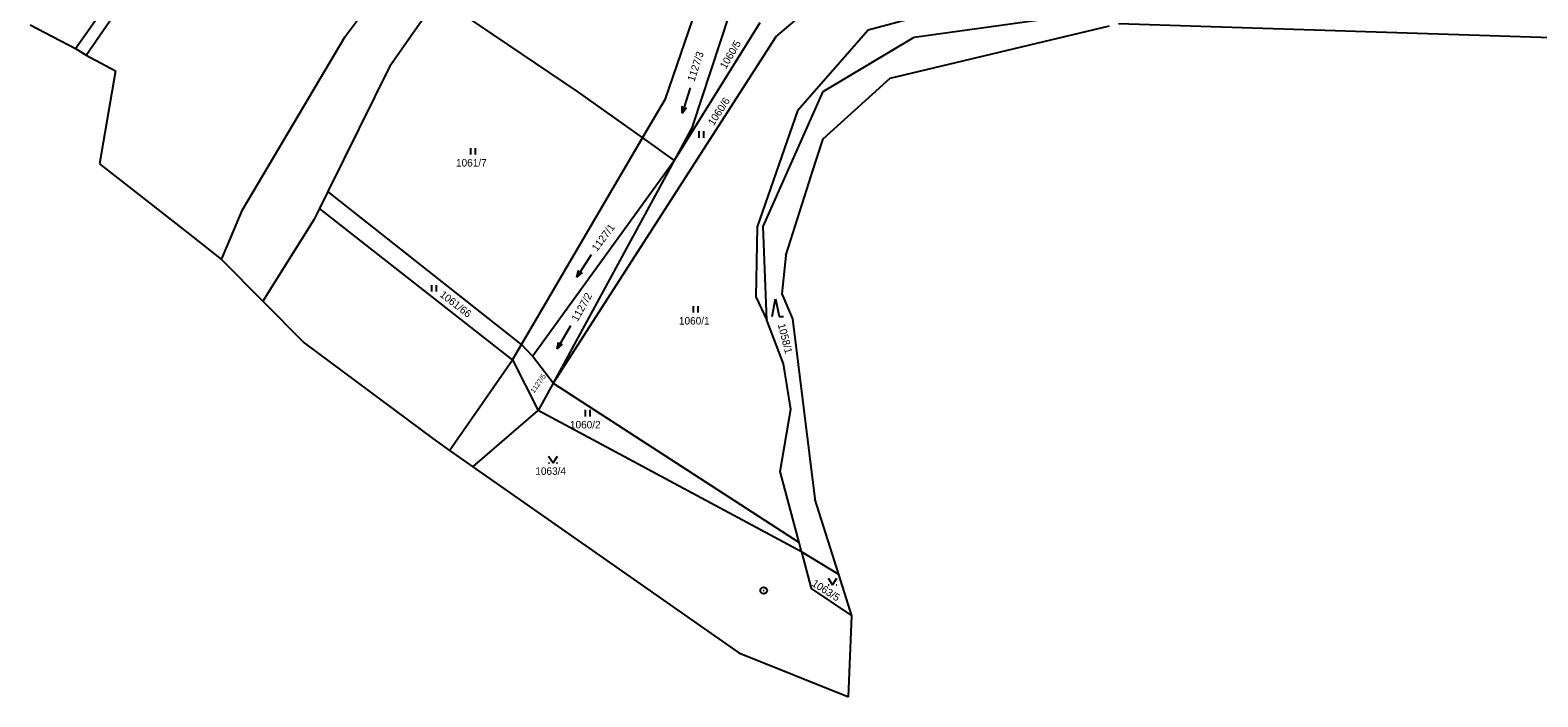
# Model space of a CAD drawing. Extents: x -794142 to -791199, y -1109267 to -1105626.
# Drawn here: x -791825.8 to -791483.8, y -1109267.2 to -1109116.1 of the extents above; entities that cross this region are included whole.
import ezdxf

# ---------------------------------------------------------------- set-up
doc = ezdxf.new("R2010")
doc.units = 0
for name, color, linetype in [('Vrstva 1', 7, 'Continuous'), ('Vrstva 14', 7, 'Continuous'), ('Vrstva 2', 7, 'Continuous'), ('Vrstva 23', 7, 'Continuous'), ('Vrstva 28', 7, 'Continuous'), ('Vrstva 4', 7, 'Continuous')]:
    doc.layers.add(name, color=color, linetype=linetype)

msp = doc.modelspace()

# ---------------------------------------------------------------- linework, layer by layer
at = {"layer": 'Vrstva 1'}
for p, q in [((-791815.6, -1109120.24), (-791790.6, -1109084.9)), ((-791813.15, -1109121.71), (-791788.95, -1109086.5)), ((-791754.39, -1109117.47), (-791732.12, -1109087.48)), ((-791587.21, -1109103.02), (-791635.72, -1109116.06)), ((-791656.65, -1109117.54), (-791641.85, -1109104.99)), ((-791744.18, -1109124.03), (-791733.38, -1109108.6)), ((-791733.38, -1109108.6), (-791701.74, -1109129.93)), ((-791681.73, -1109131.6), (-791673.74, -1109108.45)), ((-791675.53, -1109137.75), (-791667.17, -1109112.51)), ((-791625.28, -1109117.66), (-791582.71, -1109111.72)), ((-791777.65, -1109156.78), (-791754.39, -1109117.47)), ((-791656.65, -1109117.54), (-791707.2, -1109196.07)), ((-791660.34, -1109114.37), (-791679.78, -1109145.58)), ((-791635.72, -1109116.06), (-791651.74, -1109134.32)), ((-791645.91, -1109129.97), (-791625.28, -1109117.66)), ((-791744.18, -1109124.03), (-791758.35, -1109152.66)), ((-791701.74, -1109129.93), (-791686.94, -1109140.48)), ((-791659.53, -1109160.6), (-791645.91, -1109129.97)), ((-791686.94, -1109140.48), (-791681.73, -1109131.6)), ((-791651.74, -1109134.32), (-791660.94, -1109160.64)), ((-791675.53, -1109137.75), (-791679.78, -1109145.58)), ((-791714.38, -1109187.3), (-791686.94, -1109140.48)), ((-791686.94, -1109140.48), (-791679.78, -1109145.58)), ((-791711.87, -1109189.98), (-791679.78, -1109145.58)), ((-791679.78, -1109145.58), (-791707.2, -1109196.07)), ((-791758.35, -1109152.66), (-791760.23, -1109156.47)), ((-791714.38, -1109187.3), (-791758.35, -1109152.66)), ((-791781.19, -1109165.05), (-791777.65, -1109156.78)), ((-791760.23, -1109156.47), (-791761.5, -1109159.03)), ((-791716.43, -1109190.8), (-791760.23, -1109156.47)), ((-791761.5, -1109159.03), (-791773.09, -1109177.5)), ((-791660.94, -1109160.64), (-791661.25, -1109176.51)), ((-791658.73, -1109181.8), (-791659.53, -1109160.6)), ((-791782.44, -1109168.07), (-791781.19, -1109165.05)), ((-791661.25, -1109176.51), (-791658.73, -1109181.8)), ((-791654.92, -1109191.68), (-791658.73, -1109181.8)), ((-791716.43, -1109190.8), (-791714.38, -1109187.3)), ((-791711.87, -1109189.98), (-791714.38, -1109187.3)), ((-791716.43, -1109190.8), (-791710.57, -1109202.27)), ((-791707.2, -1109196.07), (-791711.87, -1109189.98)), ((-791653.31, -1109201.98), (-791654.92, -1109191.68)), ((-791707.2, -1109196.07), (-791710.57, -1109202.27)), ((-791707.2, -1109196.07), (-791651.41, -1109232.19)), ((-791650.84, -1109234.31), (-791710.57, -1109202.27)), ((-791655.69, -1109216.11), (-791653.31, -1109201.98)), ((-791651.41, -1109232.19), (-791655.69, -1109216.11)), ((-791650.84, -1109234.31), (-791651.41, -1109232.19)), ((-791650.84, -1109234.31), (-791648.67, -1109242.66)), ((-791642.41, -1109239.49), (-791650.84, -1109234.31)), ((-791648.67, -1109242.66), (-791639.45, -1109248.85))]:
    msp.add_line(p, q, dxfattribs=at)
at = {"layer": 'Vrstva 2'}
for p, q in [((-791730.72, -1109211.36), (-791716.43, -1109190.8)), ((-791725.4, -1109215.08), (-791710.57, -1109202.27))]:
    msp.add_line(p, q, dxfattribs=at)
at = {"layer": 'Vrstva 23'}
for p, q in [((-791676.085, -1109129.119), (-791677.894, -1109134.84)), ((-791677.894, -1109134.84), (-791677.918, -1109133.259)), ((-791677.894, -1109134.84), (-791676.965, -1109133.56)), ((-791674.1, -1109140.43), (-791674.1, -1109138.93)), ((-791673.1, -1109138.93), (-791673.1, -1109140.43)), ((-791725.91, -1109144.27), (-791725.91, -1109142.77)), ((-791724.91, -1109142.77), (-791724.91, -1109144.27)), ((-791698.582, -1109166.957), (-791701.797, -1109172.022)), ((-791701.797, -1109172.022), (-791701.415, -1109170.488)), ((-791701.797, -1109172.022), (-791700.571, -1109171.024)), ((-791734.72, -1109175.33), (-791734.72, -1109173.83)), ((-791733.72, -1109173.83), (-791733.72, -1109175.33)), ((-791675.38, -1109180.09), (-791675.38, -1109178.59)), ((-791674.38, -1109178.59), (-791674.38, -1109180.09)), ((-791657.54, -1109180.93), (-791656.74, -1109176.93)), ((-791656.74, -1109176.93), (-791655.94, -1109180.93)), ((-791655.94, -1109180.93), (-791654.94, -1109180.93)), ((-791703.292, -1109183.11), (-791706.287, -1109188.309)), ((-791706.287, -1109188.309), (-791705.971, -1109186.76)), ((-791706.287, -1109188.309), (-791705.105, -1109187.259)), ((-791699.88, -1109203.64), (-791699.88, -1109202.14)), ((-791698.88, -1109202.14), (-791698.88, -1109203.64)), ((-791708.23, -1109212.66), (-791707.23, -1109214.16)), ((-791707.23, -1109214.16), (-791706.23, -1109212.66)), ((-791708.23, -1109214.16), (-791708.03, -1109214.16)), ((-791706.43, -1109214.16), (-791706.23, -1109214.16)), ((-791644.81, -1109240.3), (-791643.81, -1109241.8)), ((-791643.81, -1109241.8), (-791642.81, -1109240.3)), ((-791644.81, -1109241.8), (-791644.61, -1109241.8)), ((-791643.01, -1109241.8), (-791642.81, -1109241.8))]:
    msp.add_line(p, q, dxfattribs=at)
at = {"layer": 'Vrstva 28'}
for radius in [0.75, 0.01]:
    msp.add_circle((-791659.43, -1109243.11), radius, dxfattribs=at)
at = {"layer": 'Vrstva 4'}
for p, q in [((-791825.85, -1109114.85), (-791815.6, -1109120.24)), ((-791630.72, -1109126.97), (-791580.99, -1109115.06)), ((-791578.9, -1109114.56), (-791466.68, -1109118.19)), ((-791815.6, -1109120.24), (-791813.15, -1109121.71)), ((-791813.15, -1109121.71), (-791806.47, -1109125.24)), ((-791806.47, -1109125.24), (-791810.1, -1109146.36)), ((-791645.96, -1109140.68), (-791630.72, -1109126.97)), ((-791648.41, -1109148.32), (-791645.96, -1109140.68)), ((-791810.1, -1109146.36), (-791790.36, -1109161.8)), ((-791649.11, -1109150.49), (-791648.41, -1109148.32)), ((-791654.4, -1109167.16), (-791649.11, -1109150.49)), ((-791790.36, -1109161.8), (-791782.44, -1109168.07)), ((-791782.44, -1109168.07), (-791773.09, -1109177.5)), ((-791773.09, -1109177.5), (-791763.7, -1109186.97)), ((-791763.7, -1109186.97), (-791734.46, -1109208.6)), ((-791734.46, -1109208.6), (-791730.72, -1109211.36)), ((-791730.72, -1109211.36), (-791725.4, -1109215.08)), ((-791725.4, -1109215.08), (-791665.1, -1109257.24)), ((-791642.41, -1109239.49), (-791647.85, -1109222.3)), ((-791639.45, -1109248.85), (-791642.41, -1109239.49)), ((-791640.19, -1109267.19), (-791639.45, -1109248.85)), ((-791665.1, -1109257.24), (-791640.19, -1109267.19))]:
    msp.add_line(p, q, dxfattribs=at)
msp.add_lwpolyline([(-791654.4, -1109167.16), (-791655.35, -1109175.82), (-791652.9, -1109181.47), (-791647.85, -1109222.3)], dxfattribs=at)

# ---------------------------------------------------------------- texts
at = {"layer": 'Vrstva 14'}
for s, height, rotation, p in [('1127/3', 1.7, 71.66331, (-791675.179, -1109127.849)), ('1060/5', 1.7, 59.47389, (-791668.021, -1109125.008)), ('1060/6', 1.7, 56.9079, (-791670.785, -1109137.849)), ('1127/1', 1.7, 53.33193, (-791697.239, -1109166.35)), ('1061/66', 1.7, 322.27938, (-791733.075, -1109176.298)), ('1127/2', 1.7, 60.82308, (-791701.669, -1109182.261)), ('1058/1', 1.7, 284.30694, (-791656.244, -1109182.795)), ('1127/5', 1.14, 54.97209, (-791711.523, -1109198.452)), ('1063/5', 1.7, 327.33612, (-791648.678, -1109241.884))]:
    msp.add_text(s, height=height, rotation=rotation, dxfattribs=at).set_placement(p)
for s, p in [('1061/7', (-791729.232, -1109146.97)), ('1060/1', (-791678.655, -1109182.79)), ('1060/2', (-791703.381, -1109206.34)), ('1063/4', (-791711.238, -1109216.86))]:
    msp.add_text(s, height=1.7, dxfattribs=at).set_placement(p)

doc.saveas('drawing.dxf')
